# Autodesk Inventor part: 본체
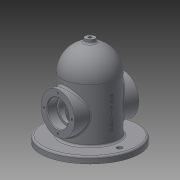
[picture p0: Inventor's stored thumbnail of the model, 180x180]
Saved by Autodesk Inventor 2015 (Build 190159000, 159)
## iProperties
Created: 2019-11
Part Number: 본체
Material: 일반
Document SubType Name: Modeling
Designer: LINEART-SSD.D4.16.06
Density: 1 g/cm^3
Appearance: 기본값
Author: LINEART-SSD.D4.16.06
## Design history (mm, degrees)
sketch "스케치1"
  geometry: C1 r 70 at (0, 0); 1 further point
  constraints: 1 centre point, 1 coincident
  dimensions: "d0" = 140 diameter of C1
extrude "돌출1" new body sketch "스케치1" distance "d1" = 10; taper "d2" = 0 deg
sketch "스케치2"
  geometry: L1 (81, 50)-(50, 50); L2 (50, 50)-(50, -50); L3 (50, -50)-(81, -50); L4 (81, -50)-(81, 50); 2 further points
  constraints: 8 end point, 2 parallel, 1 horizontal, 1 horizontal alignment, 1 midpoint, 1 perpendicular
  dimensions: "d3" = 50 distance from line of L2 point (0, 0); "d4" = 100 distance of L3.end L1.start; "d5" = 62 diameter of L4 L2
revolve "회전1" sketch "스케치2" stored, may be unused: angle "d6" = 90 deg
sketch "스케치3"
  geometry: C1 r 40 at (0, 0); 1 further point
  constraints: 1 centre point, 1 coincident
  dimensions: "d7" = 80 diameter of C1
extrude "돌출2" join sketch "스케치3" distance "d8" = 80; taper "d9" = 0 deg
sketch "스케치4"
  geometry: L1 (90, -40)-(90, 40) reference; L2 (90, 0)-(130, 0); L3 (90, 0)-(90, -40); L4 (130, 0)-(90, 0); L5 (90, 0)-(90, -40); A1 r 40 centre (90, 0) between (90, -40) and (130, 0); 1 further point
  constraints: 8 end point, 2 point on circle, 1 centre point, 1 collinear, 1 horizontal alignment, 1 midpoint, 1 point on line
  dimensions: "d10" = 40 radius of A1; "d11" = 90 deg angle of L3 L2
revolve "회전2" sketch "스케치4" stored, may be unused: angle "d12" = 90 deg
sketch "스케치5"
  geometry: C1 r 30 at (0, 0); 1 further point
  constraints: 1 centre point, 1 coincident
  dimensions: "d13" = 60 diameter of C1
extrude "돌출3" cut sketch "스케치5" distance "d14" = 90; taper "d15" = 0 deg
sketch "스케치6"
  geometry: L1 (90, -30)-(90, 30) reference; L2 (0, -30)-(0, 30) reference; L3 (90, 0)-(120, 0); L4 (90, 0)-(90, -30); L5 (120, 0)-(90, 0); L6 (90, 0)-(90, -30); A1 r 30 centre (90, 0) between (90, -30) and (120, 0); 1 further point
  constraints: 8 end point, 2 point on circle, 1 centre point, 1 collinear, 1 midpoint
  dimensions: "d16" = 30 radius of A1 (derived); "d17" = 90 deg angle of L4 L3
revolve "회전3" sketch "스케치6" stored, may be unused: angle "d18" = 90 deg
sketch "스케치7"
  geometry: L1 (70, 50)-(70, 35.3); L2 (69.7, 35)-(66.5, 35); L3 (66.5, 35)-(66.5, -35); L4 (66.5, -35)-(69.7, -35); L5 (0, -30)-(90, -30) reference; L6 (70, -35.3)-(70, -50); L7 (70, -50)-(50, -50); L8 (50, -50)-(50, 50); L9 (50, 50)-(70, 50); A1 r 0.3 centre (69.7, 35.3) between (69.7, 35) and (70, 35.3); A2 r 0.3 centre (69.7, -35.3) between (70, -35.3) and (69.7, -35); 4 further points
  constraints: 16 end point, 6 perpendicular, 4 point on circle, 4 point on line, 4 tangent, 2 centre point, 1 equal radius, 1 horizontal alignment, 1 midpoint, 1 parallel, 1 vertical
  dimensions: "d19" = 15 distance of L1.start point (70, 35); "d20" = 15 distance of point (70, -35) L6.end; "d21" = 100 distance of L7.end L8.end; "d22" = 50 distance from line of point (0, 0) L8; "d23" = 33 diameter of L3 L8; "d24" = 40 diameter of L1 L8; "d25" = 40 diameter of L6 L8; "d26" = 0.3 radius of A1
revolve "회전4" sketch "스케치7" stored, may be unused: angle "d27" = 90 deg
sketch "스케치8"
  geometry: C1 r 20 at (0, 0) reference; C2 r 31 at (0, 0) reference; 2 further points
  constraints: 1 vertical alignment
  dimensions: "d28" = 26 distance of point (0, 26) C1.centre
hole "구멍1" sketch "스케치8" at (0, 26) diameter "d29" = 3.242; stored, may be unused: countersink angle "d33" = 90 deg, drill point angle "d35" = 118 deg; dims "d30" = 8, "d31" = 4, "d32" = 2, "d34" = 10
node "작업 평면1"
node "작업 평면2"
sketch "스케치9"
  geometry: C1 r 7.5 at (0, 0); 1 further point
  constraints: 1 centre point, 1 coincident
  dimensions: "d39" = 15 diameter of C1
extrude "돌출4" join sketch "스케치9" stored distance "d40" = 10; taper "d41" = 0 deg
sketch "스케치10"
  geometry: C1 r 7.5 at (0, 0) reference; 2 further points
  constraints: 1 coincident
hole "구멍2" sketch "스케치10" at (0, 0) diameter "d42" = 5.188; stored, may be unused: countersink angle "d46" = 90 deg, drill point angle "d48" = 118 deg; dims "d43" = 12, "d44" = 4, "d45" = 2, "d47" = 16
sketch "스케치11"
  geometry: C1 r 70 at (0, 0) reference; 2 further points
  constraints: 1 horizontal alignment
  dimensions: "d49" = 55 distance of point (0, 0) point (-55, 0)
hole "구멍3" sketch "스케치11" at (-55, 0) diameter "d50" = 9; stored, may be unused: countersink angle "d54" = 90 deg, drill point angle "d56" = 118 deg; dims "d51" = 12, "d52" = 4, "d53" = 2, "d55" = 16
node "작업 평면3"
sketch "스케치12"
  geometry: L1 (-10, 70)-(-10, -70) reference; 2 further points
  constraints: 1 horizontal alignment, 1 other
  dimensions: "d60" = 50 distance from line of L1 point (40, 0)
feature "엠보싱1" sketch "스케치12" dims "d1" = 10, "d2" = 0, "d61" = 0.5, "d62" = 0
chamfer "모따기1" distance "d63" = 1; stored, may be unused: second distance "d64" = 2, angle "d65" = 45 deg
chamfer "모따기2" distance "d66" = 1; stored, may be unused: second distance "d67" = 2, angle "d68" = 45 deg
fillet "모깎기1" dims "d69" = 3
node "솔리드1"
pattern_circular "원형 패턴1" dims angle "d37" = 360 deg
mirror "대칭1"
pattern_circular "원형 패턴2" dims angle "d58" = 360 deg
node "투영된 루프1"
node "투영된 루프2"
